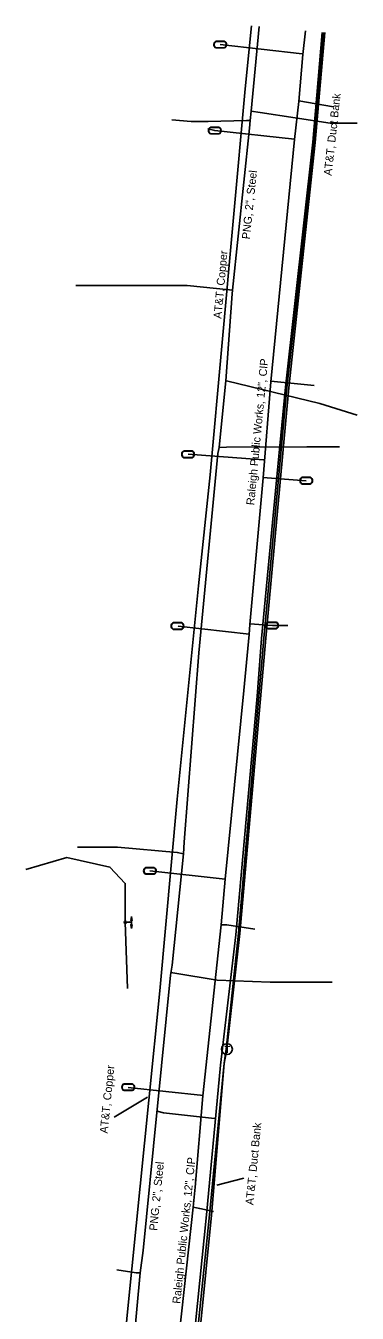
# Model space of a CAD drawing. Extents: x 2070721 to 2083039, y 729290 to 737883.
# Drawn here: x 2082371 to 2082537, y 737239 to 737883 of the extents above; entities that cross this region are included whole.
import ezdxf

# ---------------------------------------------------------------- set-up
doc = ezdxf.new("R2010")
doc.units = 0
for name, color, linetype in [('Exist Utilities Gas UG Line SUE Cogo Point CELL', 7, 'Continuous'), ('Exist Utilities Gas UG Line SUE LOS B Cogo Comment', 7, 'Continuous'), ('Exist Utilities Gas Valve Cogo Elevation', 7, 'Continuous'), ('Exist Utilities Power Pole CELL', 7, 'Continuous'), ('Exist Utilities Power Pole Cogo Elevation', 7, 'Continuous'), ('Exist Utilities Power UG Cable Cogo Point CELL', 7, 'Continuous'), ('Exist Utilities Telephone UG Cable SUE LOS C Cogo Point CELL', 7, 'Continuous'), ('Exist Utilities Telephone UG FO Cogo Point CELL', 7, 'Continuous'), ('Exist Utilities TV Pedestal Cogo Elevation', 7, 'Continuous'), ('Exist Utilities TV Pedestal Cogo Number', 7, 'Continuous'), ('Exist Utilities TV UG Cable Cogo Point CELL', 7, 'Continuous'), ('Exist Utilities TV UG Cable SUE LOS C Cogo Comment', 7, 'Continuous'), ('Exist Utilities TV UG Cable SUE LOS C Cogo Point CELL', 7, 'Continuous'), ('Exist Utilities Water Manhole Cogo Elevation', 7, 'Continuous'), ('Exist Utilities Water Meter Cogo Elevation', 7, 'Continuous'), ('Exist Utilities Water Meter Cogo Number', 7, 'Continuous')]:
    doc.layers.add(name, color=color, linetype=linetype)

msp = doc.modelspace()

# ---------------------------------------------------------------- linework, layer by layer
at = {"layer": 'Exist Utilities Gas Valve Cogo Elevation'}
msp.add_line((2082431.74, 737347.15), (2082415.02, 737337.25), dxfattribs=at)
at = {"layer": 'Exist Utilities Power Pole CELL'}
for points in [[(2082439.59, 737056.02), (2082445.06, 737108.02), (2082449.98, 737178.42), (2082461.23, 737288.47), (2082468.24, 737363.11), (2082475.86, 737428.31), (2082486.51, 737547.46), (2082488.71, 737576.37), (2082496.01, 737653.67), (2082500.6, 737701.89), (2082514.35, 737824.3), (2082518.96, 737879.18)], [(2082442.18, 737054.68), (2082447.39, 737106.94), (2082452.67, 737177.7), (2082463.63, 737288.2), (2082470.01, 737364.08), (2082471.45, 737371.14), (2082477.93, 737428.92), (2082490.82, 737576.45), (2082502.28, 737701.6), (2082515.51, 737824.17), (2082520.25, 737879.05)]]:
    msp.add_lwpolyline(points, dxfattribs=at)
at = {"layer": 'Exist Utilities Power Pole Cogo Elevation'}
msp.add_lwpolyline([(2082420.64, 737434.54), (2082420.64, 737453.94), (2082412.95, 737462.12), (2082391.51, 737466.92), (2082370.92, 737460.99)], dxfattribs=at)
at = {"layer": 'Exist Utilities Power UG Cable Cogo Point CELL'}
for p, q in [((2082420.64, 737434.54), (2082423.72, 737434.54)), ((2082420.64, 737434.54), (2082420.64, 737434.54)), ((2082423.72, 737431.4), (2082423.72, 737437.37)), ((2082423.72, 737434.54), (2082423.72, 737431.4))]:
    msp.add_line(p, q, dxfattribs=at)
for points in [[(2082423.72, 737431.4), (2082423.38, 737433.37), (2082423.72, 737432.95), (2082424.03, 737433.34)], [(2082423.72, 737437.37), (2082424.06, 737435.4), (2082423.72, 737435.82), (2082423.42, 737435.43)]]:
    msp.add_lwpolyline(points, close=True, dxfattribs=at)
msp.add_circle((2082420.64, 737434.54), 0.517, dxfattribs=at)
at = {"layer": 'Exist Utilities Telephone UG Cable SUE LOS C Cogo Point CELL'}
msp.add_circle((2082471.41, 737371.18), 2.72, dxfattribs=at)
at = {"layer": 'Exist Utilities Telephone UG FO Cogo Point CELL'}
for p, q in [((2082468.04, 737873.1), (2082468.04, 737873.1)), ((2082465.38, 737830.14), (2082465.38, 737830.14)), ((2082451.98, 737668.4), (2082451.98, 737668.4)), ((2082511.04, 737655.21), (2082511.04, 737655.21)), ((2082446.7, 737582.59), (2082446.7, 737582.59)), ((2082493.96, 737582.86), (2082493.96, 737582.86)), ((2082432.96, 737460.25), (2082432.96, 737460.25)), ((2082422.1, 737352.17), (2082422.1, 737352.17))]:
    msp.add_line(p, q, dxfattribs=at)
for points in [[(2082470.08, 737871.54), (2082465.98, 737871.54)], [(2082470.08, 737871.4), (2082465.98, 737871.4)], [(2082466.01, 737874.8), (2082470.08, 737874.8)], [(2082466.01, 737874.66), (2082470.08, 737874.66)], [(2082463.34, 737831.84), (2082467.41, 737831.84)], [(2082463.34, 737831.7), (2082467.41, 737831.7)], [(2082467.41, 737828.58), (2082463.31, 737828.58)], [(2082467.41, 737828.44), (2082463.31, 737828.44)], [(2082449.94, 737670.1), (2082454.02, 737670.1)], [(2082449.94, 737669.97), (2082454.02, 737669.97)], [(2082454.02, 737666.84), (2082449.92, 737666.84)], [(2082454.02, 737666.7), (2082449.92, 737666.7)], [(2082509, 737656.91), (2082513.08, 737656.91)], [(2082509, 737656.77), (2082513.08, 737656.77)], [(2082513.08, 737653.65), (2082508.98, 737653.65)], [(2082513.08, 737653.51), (2082508.98, 737653.51)], [(2082448.74, 737581.03), (2082444.64, 737581.03)], [(2082448.74, 737580.89), (2082444.64, 737580.89)], [(2082444.66, 737584.29), (2082448.74, 737584.29)], [(2082444.66, 737584.15), (2082448.74, 737584.15)], [(2082496, 737581.29), (2082491.9, 737581.29)], [(2082496, 737581.16), (2082491.9, 737581.16)], [(2082491.92, 737584.56), (2082496, 737584.56)], [(2082491.92, 737584.42), (2082496, 737584.42)], [(2082435, 737458.69), (2082430.9, 737458.69)], [(2082435, 737458.55), (2082430.9, 737458.55)], [(2082430.92, 737461.95), (2082435, 737461.95)], [(2082430.92, 737461.82), (2082435, 737461.82)], [(2082420.06, 737353.87), (2082424.14, 737353.87)], [(2082424.14, 737350.61), (2082420.04, 737350.61)], [(2082424.14, 737350.47), (2082420.04, 737350.47)], [(2082420.06, 737353.73), (2082424.14, 737353.73)]]:
    msp.add_lwpolyline(points, dxfattribs=at)
for centre, radius, start, end in [((2082466.74, 737873.09), 1.86, 113.17804, 245.97939), ((2082466.75, 737873.09), 1.73, 115.30093, 243.78236), ((2082469.34, 737873.1), 1.86, 293.64832, 66.30838), ((2082469.35, 737873.1), 1.73, 295.12717, 64.87283), ((2082464.07, 737830.13), 1.86, 113.17804, 245.97939), ((2082464.08, 737830.13), 1.73, 115.30093, 243.78236), ((2082466.67, 737830.14), 1.86, 293.64832, 66.30838), ((2082466.68, 737830.14), 1.73, 295.12717, 64.87283), ((2082450.67, 737668.4), 1.86, 113.17804, 245.97939), ((2082450.68, 737668.4), 1.73, 115.30093, 243.78236), ((2082453.27, 737668.4), 1.86, 293.64832, 66.30838), ((2082453.28, 737668.4), 1.73, 295.12717, 64.87283), ((2082509.73, 737655.2), 1.86, 113.17804, 245.97939), ((2082509.74, 737655.2), 1.73, 115.30093, 243.78236), ((2082512.33, 737655.21), 1.86, 293.64832, 66.30838), ((2082512.34, 737655.21), 1.73, 295.12717, 64.87283), ((2082445.39, 737582.58), 1.86, 113.17804, 245.97939), ((2082445.4, 737582.58), 1.73, 115.30093, 243.78236), ((2082447.99, 737582.59), 1.86, 293.64832, 66.30838), ((2082448.01, 737582.59), 1.73, 295.12717, 64.87283), ((2082492.65, 737582.85), 1.86, 113.17804, 245.97939), ((2082492.66, 737582.85), 1.73, 115.30093, 243.78236), ((2082495.25, 737582.86), 1.86, 293.64832, 66.30838), ((2082495.27, 737582.86), 1.73, 295.12717, 64.87283), ((2082431.65, 737460.25), 1.86, 113.17804, 245.97939), ((2082431.67, 737460.25), 1.73, 115.30093, 243.78236), ((2082434.25, 737460.25), 1.86, 293.64832, 66.30838), ((2082434.27, 737460.25), 1.73, 295.12717, 64.87283), ((2082420.79, 737352.17), 1.86, 113.17804, 245.97939), ((2082423.39, 737352.17), 1.86, 293.64832, 66.30838), ((2082420.8, 737352.17), 1.73, 115.30093, 243.78236), ((2082423.41, 737352.17), 1.73, 295.12717, 64.87283)]:
    msp.add_arc(centre, radius, start, end, dxfattribs=at)
at = {"layer": 'Exist Utilities TV Pedestal Cogo Elevation'}
for p, q in [((2082468.06, 737873.13), (2082509.02, 737868.45)), ((2082524.7, 737842.03), (2082507.32, 737845.03)), ((2082514.95, 737702.79), (2082493.35, 737704.86)), ((2082489.64, 737665.56), (2082451.98, 737668.37)), ((2082511.02, 737655.15), (2082489.28, 737656.77)), ((2082447.04, 737582.55), (2082482.45, 737578.5)), ((2082432.97, 737460.24), (2082470.51, 737456.09)), ((2082459.64, 737347.95), (2082422.09, 737352.01))]:
    msp.add_line(p, q, dxfattribs=at)
for points in [[(2082454.53, 737292.18), (2082455.59, 737302.27), (2082459.43, 737347.81), (2082468.52, 737433.35), (2082470.51, 737456.11), (2082479.78, 737550.43), (2082482.45, 737578.36), (2082482.92, 737583.28), (2082489.45, 737656.68), (2082493.42, 737704.6), (2082505.09, 737825.65), (2082507.37, 737844.71), (2082509.28, 737868.07), (2082510.7, 737879.95)], [(2082461.84, 737830.96), (2082465.36, 737830.15), (2082505.11, 737825.87)], [(2082501.85, 737582.83), (2082494.1, 737582.84), (2082482.93, 737583.74)], [(2082485.39, 737431.2), (2082471.37, 737433.34), (2082468.52, 737433.35)], [(2082443.82, 737190.2), (2082444.22, 737192.46), (2082447.74, 737229.76), (2082454.53, 737292.18)], [(2082454.53, 737292.18), (2082457.83, 737291.52), (2082464.79, 737290.13)]]:
    msp.add_lwpolyline(points, dxfattribs=at)
at = {"layer": 'Exist Utilities TV Pedestal Cogo Number'}
for points in [[(2082487.59, 737882.13), (2082483.51, 737839.88), (2082483, 737835.22)], [(2082536.52, 737833.77), (2082522.97, 737833.77), (2082487.98, 737839.16), (2082483.51, 737839.88)], [(2082483, 737835.22), (2082481.24, 737835.18), (2082462.05, 737834.7), (2082453.63, 737834.7), (2082443.84, 737835.54)], [(2082483, 737835.22), (2082482.63, 737831.3), (2082474.13, 737750.41), (2082474.03, 737748.58)], [(2082474.13, 737750.41), (2082472.68, 737750.56), (2082451.49, 737752.71), (2082424.37, 737752.71), (2082395.96, 737752.71)], [(2082470.85, 737705.09), (2082474.03, 737748.58)], [(2082470.85, 737705.09), (2082470.63, 737703.53), (2082467.59, 737671.86)], [(2082470.85, 737705.09), (2082471.19, 737705.01), (2082517.76, 737693.69), (2082536.4, 737687.88)], [(2082449.64, 737468.69), (2082450.03, 737474.55), (2082457.42, 737569.15), (2082466.95, 737668.72), (2082467.59, 737671.86)], [(2082467.59, 737671.86), (2082471.2, 737671.88), (2082511.29, 737672.07), (2082527.62, 737672.07)], [(2082449.64, 737468.69), (2082446.6, 737469.5), (2082416.78, 737472.17), (2082396.83, 737472.17)], [(2082443.22, 737408.08), (2082444.08, 737413.12), (2082449.64, 737468.69)], [(2082443.22, 737408.08), (2082436.59, 737340.96), (2082436.42, 737339.48)], [(2082523.95, 737404.6), (2082493.06, 737404.6), (2082466.47, 737405.71), (2082445.45, 737409.06), (2082443.45, 737409.42)], [(2082436.42, 737339.48), (2082429.5, 737270.55), (2082428.12, 737259.46)], [(2082436.5, 737340.22), (2082439.81, 737339.38), (2082465.16, 737336.53)], [(2082410, 737077.78), (2082411.36, 737086.72), (2082416.51, 737136.35), (2082423.37, 737208.61), (2082428.12, 737259.46)], [(2082428.12, 737259.46), (2082426.14, 737259.33), (2082416.35, 737260.83)]]:
    msp.add_lwpolyline(points, dxfattribs=at)
at = {"layer": 'Exist Utilities TV UG Cable Cogo Point CELL'}
msp.add_lwpolyline([(2082403.44, 737082.03), (2082412.57, 737137.7), (2082418.97, 737209.91), (2082421.82, 737239.88), (2082432.43, 737345.64), (2082437.88, 737400.24), (2082446.55, 737496.08), (2082457.15, 737602.73), (2082463.04, 737658.16), (2082480.56, 737850.96), (2082483.62, 737882.51)], dxfattribs=at)
at = {"layer": 'Exist Utilities TV UG Cable SUE LOS C Cogo Comment'}
msp.add_lwpolyline([(2082421.76, 737401.42), (2082420.64, 737434.54), (2082422.94, 737434.86)], dxfattribs=at)
at = {"layer": 'Exist Utilities TV UG Cable SUE LOS C Cogo Point CELL'}
msp.add_lwpolyline([(2082440.99, 737055.64), (2082446.34, 737107.79), (2082451.46, 737177.85), (2082462.75, 737288.32), (2082470.03, 737364.09), (2082470.98, 737371.16), (2082477.18, 737429.09), (2082489.87, 737576.45), (2082501.4, 737701.55), (2082515.01, 737823.97), (2082519.76, 737879.1)], dxfattribs=at)
at = {"layer": 'Exist Utilities Water Manhole Cogo Elevation'}
msp.add_line((2082466.3, 737303.28), (2082479.79, 737306.7), dxfattribs=at)

# ---------------------------------------------------------------- texts
at = {"layer": 'Exist Utilities Gas UG Line SUE Cogo Point CELL'}
for s, rotation, p in [('Raleigh Public Works, 12", CIP', 84.49581, (2082485.02, 737642.8)), ('Raleigh Public Works, 12", CIP ', 84.02989, (2082448.1, 737243.82))]:
    msp.add_text(s, height=4, rotation=rotation, dxfattribs=at).set_placement(p)
at = {"layer": 'Exist Utilities Gas UG Line SUE LOS B Cogo Comment'}
for rotation, p in [(83.65695, (2082523.69, 737807.43)), (84.51155, (2082484.63, 737293.14))]:
    msp.add_text('AT&T, Duct Bank', height=4, rotation=rotation, dxfattribs=at).set_placement(p)
at = {"layer": 'Exist Utilities Telephone UG Cable SUE LOS C Cogo Point CELL'}
msp.add_text('T', height=3.5, dxfattribs=at).set_placement((2082470.23, 737369.17))
at = {"layer": 'Exist Utilities Water Meter Cogo Elevation'}
for rotation, p in [(83.99685, (2082482.82, 737775.68)), (84.26949, (2082436.51, 737280.3))]:
    msp.add_text('PNG, 2", Steel', height=4, rotation=rotation, dxfattribs=at).set_placement(p)
at = {"layer": 'Exist Utilities Water Meter Cogo Number'}
for rotation, p in [(84.80855, (2082468.66, 737735.97)), (84.27066, (2082411.8, 737328.92))]:
    msp.add_text('AT&T, Copper', height=4, rotation=rotation, dxfattribs=at).set_placement(p)

doc.saveas('drawing.dxf')
